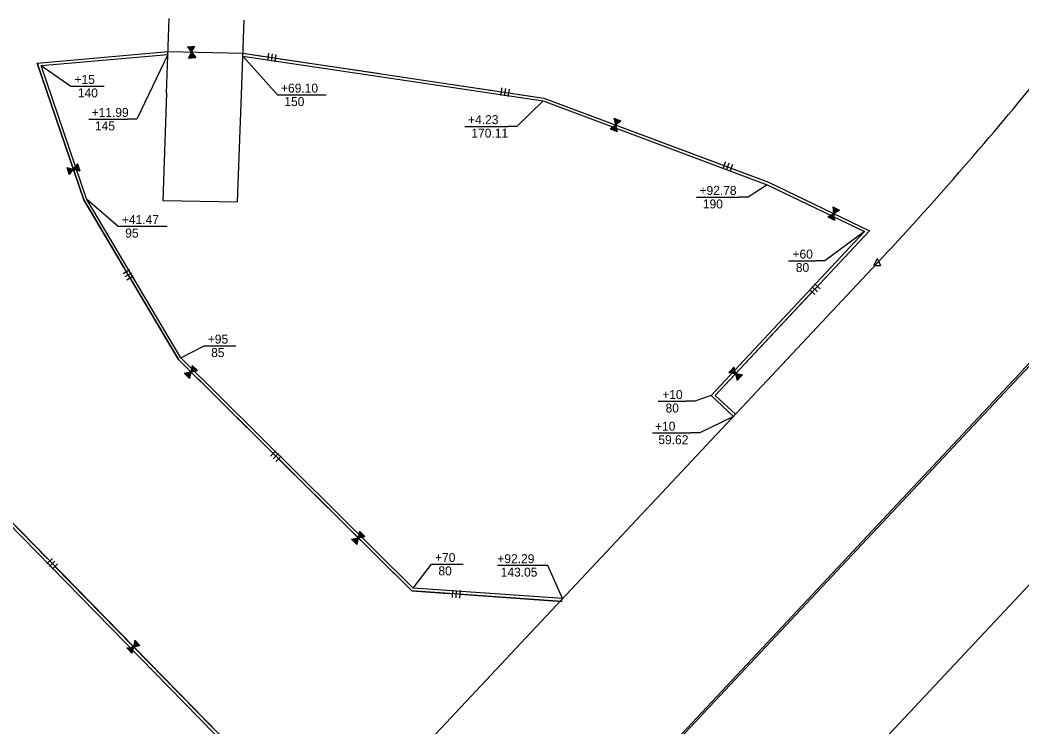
# Model space of a CAD drawing. Extents: x 979729 to 993523, y 1834148 to 1845433.
# Drawn here: x 991545 to 992215, y 1839035 to 1839507 of the extents above; entities that cross this region are included whole.
import ezdxf

# ---------------------------------------------------------------- set-up
doc = ezdxf.new("R2010")
doc.units = 0
for name, color, linetype in [('42', 7, 'Continuous'), ('51', 7, 'Continuous'), ('R_Draft', 7, 'Continuous'), ('S_EXIST_ROW', 7, 'Continuous')]:
    doc.layers.add(name, color=color, linetype=linetype)

msp = doc.modelspace()

# ---------------------------------------------------------------- linework, layer by layer
at = {"layer": '42'}
for p, q in [((991644.19, 1839486.32), (991694.18, 1839485.24)), ((991657.1, 1839489.43), (991659.92, 1839485.91)), ((991657.17, 1839489.38), (991657.2, 1839489.44)), ((991657.34, 1839489.19), (991657.5, 1839489.46)), ((991657.5, 1839488.96), (991657.8, 1839489.49)), ((991657.68, 1839488.77), (991658.1, 1839489.52)), ((991657.76, 1839481.96), (991659.92, 1839485.91)), ((991657.84, 1839488.54), (991658.39, 1839489.54)), ((991658, 1839488.31), (991658.69, 1839489.57)), ((991658.18, 1839488.11), (991658.99, 1839489.59)), ((991658.39, 1839487.98), (991659.21, 1839489.48)), ((991658.53, 1839487.71), (991659.59, 1839489.65)), ((991658.71, 1839487.52), (991659.89, 1839489.67)), ((991658.86, 1839487.27), (991660.19, 1839489.7)), ((991659.05, 1839487.1), (991660.49, 1839489.73)), ((991659.2, 1839486.85), (991660.79, 1839489.75)), ((991659.38, 1839486.65), (991661.09, 1839489.78)), ((991659.54, 1839486.42), (991661.39, 1839489.8)), ((991659.63, 1839485.34), (991662.04, 1839482.33)), ((991659.73, 1839486.25), (991661.69, 1839489.83)), ((991659.79, 1839485.54), (991662.34, 1839482.36)), ((991659.87, 1839486), (991661.99, 1839489.86)), ((991659.89, 1839485.82), (991662.64, 1839482.38)), ((991659.92, 1839485.91), (991662.09, 1839489.86)), ((991659.92, 1839485.91), (991662.74, 1839482.39)), ((991711.36, 1839485.21), (991710.63, 1839480.26)), ((991657.81, 1839482.02), (991657.85, 1839481.97)), ((991657.95, 1839482.24), (991658.15, 1839481.99)), ((991658.07, 1839482.49), (991658.45, 1839482.02)), ((991658.21, 1839482.71), (991658.75, 1839482.04)), ((991658.33, 1839482.97), (991659.05, 1839482.07)), ((991658.45, 1839483.22), (991659.35, 1839482.1)), ((991658.59, 1839483.44), (991659.64, 1839482.12)), ((991658.77, 1839483.61), (991659.84, 1839482.28)), ((991658.87, 1839483.9), (991660.24, 1839482.18)), ((991659.01, 1839484.12), (991660.54, 1839482.2)), ((991659.11, 1839484.39), (991660.84, 1839482.23)), ((991659.27, 1839484.59), (991661.14, 1839482.25)), ((991659.37, 1839484.87), (991661.44, 1839482.28)), ((991659.51, 1839485.09), (991661.74, 1839482.31)), ((991713.84, 1839484.84), (991713.1, 1839479.89)), ((991716.31, 1839484.47), (991715.57, 1839479.52)), ((991867.15, 1839462.02), (991866.41, 1839457.07)), ((991869.62, 1839461.65), (991868.88, 1839456.71)), ((991872.09, 1839461.28), (991871.36, 1839456.34)), ((991942.19, 1839441.76), (991943.22, 1839437.38)), ((991942.23, 1839441.69), (991942.28, 1839441.73)), ((991942.31, 1839441.44), (991942.56, 1839441.63)), ((991942.35, 1839441.17), (991942.84, 1839441.52)), ((991942.43, 1839440.91), (991943.13, 1839441.41)), ((991942.48, 1839440.64), (991943.41, 1839441.31)), ((991942.52, 1839440.36), (991943.69, 1839441.2)), ((991942.6, 1839440.11), (991943.97, 1839441.1)), ((991942.73, 1839439.9), (991944.12, 1839440.9)), ((991942.75, 1839439.6), (991944.53, 1839440.89)), ((991942.82, 1839439.35), (991944.81, 1839440.78)), ((991942.85, 1839439.06), (991945.1, 1839440.68)), ((991942.95, 1839438.82), (991945.38, 1839440.57)), ((991942.97, 1839438.53), (991945.66, 1839440.47)), ((991943.05, 1839438.28), (991945.94, 1839440.36)), ((991943.09, 1839438), (991946.22, 1839440.26)), ((991943.19, 1839437.77), (991946.5, 1839440.15)), ((991943.22, 1839437.48), (991946.78, 1839440.05)), ((991943.22, 1839437.38), (991946.88, 1839440.01)), ((991939.57, 1839434.74), (991943.22, 1839437.38)), ((991939.64, 1839434.77), (991939.65, 1839434.71)), ((991939.86, 1839434.91), (991939.93, 1839434.6)), ((991940.08, 1839435.09), (991940.21, 1839434.5)), ((991940.3, 1839435.22), (991940.5, 1839434.39)), ((991940.52, 1839435.4), (991940.78, 1839434.29)), ((991940.73, 1839435.58), (991941.06, 1839434.18)), ((991940.96, 1839435.72), (991941.34, 1839434.07)), ((991941.19, 1839435.8), (991941.58, 1839434.13)), ((991941.4, 1839436.01), (991941.9, 1839433.86)), ((991941.63, 1839436.15), (991942.19, 1839433.76)), ((991941.83, 1839436.35), (991942.47, 1839433.65)), ((991942.07, 1839436.46), (991942.75, 1839433.55)), ((991942.27, 1839436.67), (991943.03, 1839433.44)), ((991942.5, 1839436.81), (991943.31, 1839433.34)), ((991942.71, 1839436.99), (991943.59, 1839433.23)), ((991942.94, 1839437.1), (991943.87, 1839433.13)), ((991943.15, 1839437.3), (991944.15, 1839433.02)), ((991943.22, 1839437.38), (991944.25, 1839432.99)), ((992016.68, 1839412.55), (992014.93, 1839407.87)), ((992019.02, 1839411.68), (992017.27, 1839406.99)), ((992021.36, 1839410.8), (992019.61, 1839406.12)), ((992085.11, 1839375.82), (992088.99, 1839378.11)), ((992088.37, 1839382.57), (992088.99, 1839378.11)), ((992088.4, 1839382.5), (992088.46, 1839382.53)), ((992088.46, 1839382.24), (992088.73, 1839382.4)), ((992088.47, 1839381.96), (992089, 1839382.27)), ((992088.53, 1839381.71), (992089.27, 1839382.14)), ((992088.55, 1839381.43), (992089.54, 1839382.01)), ((992088.57, 1839381.15), (992089.81, 1839381.88)), ((992088.62, 1839380.89), (992090.08, 1839381.75)), ((992088.72, 1839380.37), (992090.62, 1839381.49)), ((992088.74, 1839380.67), (992090.21, 1839381.53)), ((992088.77, 1839379.82), (992091.16, 1839381.23)), ((992088.78, 1839380.11), (992090.89, 1839381.36)), ((992088.85, 1839379.57), (992091.43, 1839381.1)), ((992088.85, 1839379.28), (992091.7, 1839380.97)), ((992088.9, 1839379.03), (992091.97, 1839380.84)), ((992088.92, 1839378.75), (992092.24, 1839380.71)), ((992088.99, 1839378.11), (992092.88, 1839380.4)), ((992088.99, 1839378.11), (992089.62, 1839373.65)), ((992089, 1839378.5), (992092.51, 1839380.57)), ((992089, 1839378.21), (992092.78, 1839380.44)), ((992085.19, 1839375.84), (992085.2, 1839375.78)), ((992085.42, 1839375.96), (992085.47, 1839375.65)), ((992085.65, 1839376.12), (992085.74, 1839375.52)), ((992085.89, 1839376.23), (992086.01, 1839375.39)), ((992086.12, 1839376.39), (992086.28, 1839375.26)), ((992086.35, 1839376.55), (992086.55, 1839375.12)), ((992086.59, 1839376.67), (992086.82, 1839374.99)), ((992086.83, 1839376.72), (992087.07, 1839375.03)), ((992087.06, 1839376.92), (992087.36, 1839374.73)), ((992087.29, 1839377.03), (992087.63, 1839374.6)), ((992087.52, 1839377.22), (992087.9, 1839374.47)), ((992087.76, 1839377.31), (992088.17, 1839374.34)), ((992087.99, 1839377.49), (992088.44, 1839374.21)), ((992088.22, 1839377.61), (992088.71, 1839374.08)), ((992088.45, 1839377.77), (992088.99, 1839373.95)), ((992088.69, 1839377.86), (992089.26, 1839373.82)), ((992088.92, 1839378.04), (992089.53, 1839373.69)), ((992076.46, 1839324), (992072.81, 1839327.41)), ((992078.17, 1839325.82), (992074.51, 1839329.24)), ((992079.87, 1839327.65), (992076.22, 1839331.06)), ((992023.4, 1839270.93), (992018.95, 1839271.67)), ((992023.36, 1839271.02), (992019.02, 1839271.74)), ((992023.25, 1839271.3), (992019.22, 1839271.96)), ((992023.23, 1839271.55), (992019.43, 1839272.18)), ((992023.15, 1839271.82), (992019.63, 1839272.4)), ((992023.11, 1839272.08), (992019.84, 1839272.62)), ((992023, 1839272.35), (992020.04, 1839272.84)), ((992022.99, 1839272.61), (992020.25, 1839273.06)), ((992022.87, 1839272.88), (992020.45, 1839273.28)), ((992022.83, 1839273.14), (992020.66, 1839273.5)), ((992022.72, 1839273.41), (992021.03, 1839273.69)), ((992022.74, 1839273.66), (992021.07, 1839273.94)), ((992022.69, 1839273.92), (992021.28, 1839274.16)), ((992022.61, 1839274.19), (992021.48, 1839274.37)), ((992022.53, 1839274.45), (992021.69, 1839274.59)), ((992022.49, 1839274.71), (992021.89, 1839274.81)), ((992022.41, 1839274.98), (992022.1, 1839275.03)), ((992022.37, 1839275.24), (992022.3, 1839275.25)), ((992022.37, 1839275.32), (992023.4, 1839270.93)), ((992023.4, 1839270.93), (992024.43, 1839266.55)), ((992027.84, 1839270.2), (992023.4, 1839270.93)), ((992023.49, 1839270.9), (992024.5, 1839266.62)), ((992023.77, 1839270.81), (992024.7, 1839266.84)), ((992024.02, 1839270.81), (992024.91, 1839267.06)), ((992024.3, 1839270.75), (992025.11, 1839267.28)), ((992024.56, 1839270.72), (992025.32, 1839267.5)), ((992024.84, 1839270.63), (992025.52, 1839267.71)), ((992025.09, 1839270.63), (992025.73, 1839267.93)), ((992025.37, 1839270.54), (992025.93, 1839268.15)), ((992025.63, 1839270.52), (992026.14, 1839268.37)), ((992025.91, 1839270.42), (992026.31, 1839268.75)), ((992026.16, 1839270.46), (992026.55, 1839268.81)), ((992026.42, 1839270.43), (992026.75, 1839269.03)), ((992026.7, 1839270.37), (992026.96, 1839269.25)), ((992026.97, 1839270.3), (992027.16, 1839269.47)), ((992027.23, 1839270.28), (992027.37, 1839269.69)), ((992027.5, 1839270.22), (992027.57, 1839269.91)), ((992027.76, 1839270.19), (992027.78, 1839270.13))]:
    msp.add_line(p, q, dxfattribs=at)
for points in [[(991556.68, 1839478.69), (991644.19, 1839486.32)], [(991556.68, 1839478.69), (991644.19, 1839486.32), (991694.18, 1839485.24), (991708.52, 1839483.1)], [(991657.1, 1839489.43), (991662.09, 1839489.86)], [(991694.18, 1839485.24), (991895.33, 1839455.3), (992045.44, 1839399.12), (992112.88, 1839366.59)], [(991907.63, 1839118.73), (991807.07, 1839125.82), (991651.09, 1839280.5), (991587.82, 1839387.14), (991556.68, 1839478.69)], [(991657.76, 1839481.96), (991662.74, 1839482.39)], [(991715.94, 1839482), (991785.64, 1839471.62)], [(991828.17, 1839465.29), (991864.31, 1839459.92)], [(991871.72, 1839458.81), (991895.33, 1839455.3), (992013.46, 1839411.09)], [(991942.19, 1839441.76), (991946.88, 1839440.01)], [(991939.57, 1839434.74), (991944.25, 1839432.99)], [(992020.49, 1839408.46), (992045.44, 1839399.12), (992112.88, 1839366.59), (992079.76, 1839331.18)], [(991382.17, 1839394.42), (991468.64, 1839244.34), (991726.6, 1838980.6), (991714.1, 1838911.75)], [(992088.37, 1839382.57), (992092.88, 1839380.4)], [(992085.11, 1839375.82), (992089.62, 1839373.65)], [(992112.88, 1839366.59), (992009.91, 1839256.52), (992023.34, 1839243.96)], [(992074.63, 1839325.7), (992009.91, 1839256.52), (992023.34, 1839243.96)], [(992022.37, 1839275.32), (992018.95, 1839271.67)], [(992027.84, 1839270.2), (992024.43, 1839266.55)]]:
    msp.add_lwpolyline(points, dxfattribs=at)
at = {"layer": '51'}
for p, q in [((991576.48, 1839408.84), (991580.83, 1839407.69)), ((991576.55, 1839408.81), (991576.51, 1839408.76)), ((991576.8, 1839408.72), (991576.6, 1839408.47)), ((991577.07, 1839408.67), (991576.7, 1839408.19)), ((991577.32, 1839408.58), (991576.8, 1839407.9)), ((991577.59, 1839408.53), (991576.89, 1839407.62)), ((991577.86, 1839408.47), (991576.99, 1839407.33)), ((991578.12, 1839408.39), (991577.09, 1839407.05)), ((991578.32, 1839408.25), (991577.28, 1839406.9)), ((991578.62, 1839408.23), (991577.28, 1839406.48)), ((991578.87, 1839408.14), (991577.38, 1839406.2)), ((991579.16, 1839408.11), (991577.47, 1839405.91)), ((991579.39, 1839408), (991577.57, 1839405.63)), ((991579.69, 1839407.97), (991577.67, 1839405.34)), ((991579.93, 1839407.88), (991577.76, 1839405.06)), ((991580.21, 1839407.83), (991577.86, 1839404.77)), ((991580.44, 1839407.72), (991577.96, 1839404.49)), ((991580.73, 1839407.69), (991578.05, 1839404.21)), ((991580.83, 1839407.69), (991578.09, 1839404.11)), ((991583.58, 1839411.26), (991580.83, 1839407.69)), ((991580.83, 1839407.69), (991585.19, 1839406.53)), ((991580.91, 1839407.75), (991585.15, 1839406.62)), ((991581.12, 1839407.95), (991585.06, 1839406.9)), ((991581.24, 1839408.18), (991584.96, 1839407.19)), ((991581.42, 1839408.39), (991584.86, 1839407.47)), ((991581.57, 1839408.61), (991584.77, 1839407.76)), ((991581.78, 1839408.81), (991584.67, 1839408.04)), ((991581.9, 1839409.04), (991584.57, 1839408.33)), ((991582.11, 1839409.24), (991584.48, 1839408.61)), ((991582.25, 1839409.46), (991584.38, 1839408.9)), ((991582.47, 1839409.66), (991584.12, 1839409.22)), ((991582.55, 1839409.9), (991584.19, 1839409.46)), ((991582.7, 1839410.12), (991584.09, 1839409.75)), ((991582.88, 1839410.33), (991583.99, 1839410.03)), ((991583.07, 1839410.54), (991583.9, 1839410.32)), ((991583.21, 1839410.76), (991583.8, 1839410.6)), ((991583.4, 1839410.97), (991583.7, 1839410.89)), ((991583.54, 1839411.19), (991583.61, 1839411.17)), ((991618.44, 1839340.43), (991614.14, 1839337.88)), ((991619.72, 1839338.28), (991615.42, 1839335.73)), ((991620.99, 1839336.13), (991616.69, 1839333.58)), ((991655.05, 1839271.29), (991659.47, 1839272.19)), ((991655.13, 1839271.29), (991655.12, 1839271.22)), ((991655.39, 1839271.32), (991655.33, 1839271.01)), ((991655.66, 1839271.39), (991655.55, 1839270.8)), ((991655.92, 1839271.43), (991655.76, 1839270.59)), ((991656.19, 1839271.5), (991655.97, 1839270.37)), ((991656.46, 1839271.57), (991656.19, 1839270.16)), ((991656.72, 1839271.61), (991656.4, 1839269.95)), ((991656.97, 1839271.58), (991656.64, 1839269.9)), ((991657.25, 1839271.69), (991656.83, 1839269.53)), ((991657.51, 1839271.72), (991657.04, 1839269.32)), ((991657.78, 1839271.83), (991657.25, 1839269.11)), ((991658.04, 1839271.83), (991657.47, 1839268.89)), ((991658.32, 1839271.93), (991657.68, 1839268.68)), ((991658.58, 1839271.97), (991657.89, 1839268.47)), ((991658.85, 1839272.04), (991658.11, 1839268.26)), ((991659.1, 1839272.05), (991658.32, 1839268.05)), ((991659.38, 1839272.15), (991658.53, 1839267.84)), ((991659.47, 1839272.19), (991658.6, 1839267.77)), ((991660.33, 1839276.61), (991659.47, 1839272.19)), ((991659.47, 1839272.19), (991663.88, 1839273.09)), ((991659.51, 1839272.28), (991663.81, 1839273.16)), ((991659.61, 1839272.81), (991663.39, 1839273.58)), ((991659.61, 1839272.56), (991663.6, 1839273.37)), ((991659.68, 1839273.08), (991663.17, 1839273.8)), ((991659.71, 1839273.34), (991662.96, 1839274.01)), ((991659.81, 1839273.62), (991662.75, 1839274.22)), ((991659.82, 1839273.88), (991662.53, 1839274.43)), ((991659.92, 1839274.15), (991662.32, 1839274.64)), ((991659.95, 1839274.41), (991662.11, 1839274.85)), ((991660.03, 1839274.94), (991661.68, 1839275.28)), ((991660.06, 1839275.2), (991661.47, 1839275.49)), ((991660.06, 1839274.69), (991661.73, 1839275.03)), ((991660.13, 1839275.47), (991661.25, 1839275.7)), ((991660.2, 1839275.74), (991661.04, 1839275.91)), ((991660.23, 1839276), (991660.83, 1839276.12)), ((991660.3, 1839276.27), (991660.61, 1839276.33)), ((991660.34, 1839276.53), (991660.4, 1839276.55)), ((991716.26, 1839219.39), (991712.74, 1839215.84)), ((991718.03, 1839217.63), (991714.51, 1839214.08)), ((991719.81, 1839215.87), (991716.29, 1839212.32)), ((991772.17, 1839165.71), (991771.3, 1839161.29)), ((991771.78, 1839163.51), (991773.94, 1839163.95)), ((991771.86, 1839164.04), (991773.51, 1839164.38)), ((991771.89, 1839164.3), (991773.3, 1839164.59)), ((991771.89, 1839163.79), (991773.57, 1839164.13)), ((991771.96, 1839164.57), (991773.09, 1839164.8)), ((991772.04, 1839164.84), (991772.87, 1839165.01)), ((991772.07, 1839165.1), (991772.66, 1839165.22)), ((991772.14, 1839165.37), (991772.45, 1839165.43)), ((991772.17, 1839165.63), (991772.23, 1839165.64)), ((991766.89, 1839160.38), (991771.3, 1839161.29)), ((991766.97, 1839160.38), (991766.95, 1839160.32)), ((991767.23, 1839160.42), (991767.17, 1839160.11)), ((991767.5, 1839160.49), (991767.38, 1839159.9)), ((991767.76, 1839160.52), (991767.59, 1839159.68)), ((991768.03, 1839160.6), (991767.81, 1839159.47)), ((991768.3, 1839160.67), (991768.02, 1839159.26)), ((991768.56, 1839160.71), (991768.23, 1839159.05)), ((991768.81, 1839160.68), (991768.48, 1839159)), ((991769.08, 1839160.79), (991768.66, 1839158.63)), ((991769.34, 1839160.82), (991768.87, 1839158.41)), ((991769.62, 1839160.92), (991769.09, 1839158.2)), ((991769.88, 1839160.93), (991769.3, 1839157.99)), ((991770.15, 1839161.03), (991769.51, 1839157.78)), ((991770.41, 1839161.07), (991769.73, 1839157.57)), ((991770.68, 1839161.14), (991769.94, 1839157.36)), ((991770.94, 1839161.15), (991770.15, 1839157.15)), ((991771.21, 1839161.25), (991770.37, 1839156.93)), ((991771.3, 1839161.29), (991770.44, 1839156.86)), ((991771.3, 1839161.29), (991775.72, 1839162.19)), ((991771.34, 1839161.38), (991775.65, 1839162.26)), ((991771.44, 1839161.91), (991775.22, 1839162.68)), ((991771.44, 1839161.66), (991775.43, 1839162.47)), ((991771.52, 1839162.18), (991775.01, 1839162.89)), ((991771.55, 1839162.44), (991774.79, 1839163.11)), ((991771.65, 1839162.97), (991774.37, 1839163.53)), ((991771.65, 1839162.72), (991774.58, 1839163.32)), ((991771.75, 1839163.25), (991774.16, 1839163.74)), ((991566.87, 1839147.49), (991563.29, 1839143.99)), ((991568.61, 1839145.7), (991565.04, 1839142.21)), ((991570.36, 1839143.91), (991566.79, 1839140.42)), ((991834.31, 1839126.4), (991833.96, 1839121.42)), ((991836.8, 1839126.23), (991836.45, 1839121.24)), ((991839.3, 1839126.05), (991838.94, 1839121.07)), ((991621.95, 1839092.96), (991621.02, 1839088.55)), ((991621.28, 1839089.7), (991624.54, 1839090.31)), ((991621.38, 1839089.97), (991624.33, 1839090.53)), ((991621.39, 1839090.23), (991624.12, 1839090.74)), ((991621.5, 1839090.5), (991623.91, 1839090.96)), ((991621.53, 1839090.76), (991623.7, 1839091.17)), ((991621.62, 1839091.29), (991623.28, 1839091.6)), ((991621.64, 1839091.04), (991623.32, 1839091.36)), ((991621.65, 1839091.55), (991623.07, 1839091.82)), ((991621.73, 1839091.82), (991622.86, 1839092.03)), ((991621.8, 1839092.09), (991622.65, 1839092.25)), ((991621.84, 1839092.35), (991622.43, 1839092.46)), ((991621.92, 1839092.62), (991622.23, 1839092.68)), ((991621.95, 1839092.88), (991622.01, 1839092.89)), ((991616.59, 1839087.71), (991621.02, 1839088.55)), ((991616.67, 1839087.71), (991616.65, 1839087.65)), ((991616.93, 1839087.74), (991616.86, 1839087.43)), ((991617.2, 1839087.81), (991617.07, 1839087.22)), ((991617.46, 1839087.84), (991617.28, 1839087)), ((991617.73, 1839087.91), (991617.49, 1839086.79)), ((991618, 1839087.98), (991617.7, 1839086.57)), ((991618.26, 1839088.01), (991617.91, 1839086.36)), ((991618.51, 1839087.98), (991618.16, 1839086.31)), ((991618.79, 1839088.08), (991618.33, 1839085.93)), ((991619.05, 1839088.11), (991618.54, 1839085.71)), ((991619.33, 1839088.21), (991618.75, 1839085.5)), ((991619.58, 1839088.21), (991618.96, 1839085.28)), ((991619.86, 1839088.31), (991619.17, 1839085.07)), ((991620.12, 1839088.34), (991619.38, 1839084.85)), ((991620.39, 1839088.41), (991619.59, 1839084.64)), ((991620.65, 1839088.41), (991619.8, 1839084.42)), ((991620.92, 1839088.51), (991620.01, 1839084.21)), ((991621.02, 1839088.55), (991620.08, 1839084.14)), ((991621.02, 1839088.55), (991625.45, 1839089.38)), ((991621.06, 1839088.64), (991625.38, 1839089.45)), ((991621.16, 1839088.91), (991625.17, 1839089.67)), ((991621.17, 1839089.17), (991624.96, 1839089.88)), ((991621.24, 1839089.44), (991624.75, 1839090.1))]:
    msp.add_line(p, q, dxfattribs=at)
for points in [[(991556.68, 1839478.69), (991587.82, 1839387.14), (991615.01, 1839341.3)], [(991907.77, 1839120.72), (991807.95, 1839127.76), (991652.68, 1839281.74), (991589.65, 1839387.98), (991559.39, 1839476.92), (991644.12, 1839484.31)], [(991694.11, 1839483.22), (991894.83, 1839453.35), (992044.65, 1839397.28), (992109.56, 1839365.97)], [(991576.48, 1839408.84), (991578.09, 1839404.11)], [(991583.58, 1839411.26), (991585.19, 1839406.53)], [(991381, 1839392.44), (991467.04, 1839243.12), (991724.44, 1838979.94), (991712.13, 1838912.1)], [(992109.56, 1839365.97), (992007.09, 1839256.43), (992021.97, 1839242.5)], [(991618.84, 1839334.85), (991651.09, 1839280.5), (991712.72, 1839219.38)], [(991655.05, 1839271.29), (991658.6, 1839267.77)], [(991660.33, 1839276.61), (991663.88, 1839273.09)], [(991461.36, 1839256.97), (991468.64, 1839244.34), (991563.33, 1839147.53)], [(991718.05, 1839214.1), (991807.07, 1839125.82), (991831.64, 1839124.09)], [(991772.17, 1839165.71), (991775.72, 1839162.19)], [(991766.89, 1839160.38), (991770.44, 1839156.86)], [(991568.58, 1839142.17), (991673.46, 1839034.93)], [(991839.12, 1839123.56), (991907.63, 1839118.73)], [(991621.95, 1839092.96), (991625.45, 1839089.38)], [(991616.59, 1839087.71), (991620.08, 1839084.14)]]:
    msp.add_lwpolyline(points, dxfattribs=at)
at = {"layer": 'R_Draft'}
for p, q in [((991585.31, 1839463.21), (991601.46, 1839463.21)), ((991723.31, 1839457.4), (991749.89, 1839457.4)), ((991591.35, 1839441.16), (991617.39, 1839441.16)), ((991842.59, 1839436.32), (991871.21, 1839436.32)), ((991997.26, 1839389.01), (992025.88, 1839389.01)), ((991616.97, 1839369.53), (991643.55, 1839369.53)), ((992058.77, 1839346.48), (992077.2, 1839346.48)), ((991674.38, 1839289.64), (991689.49, 1839289.64)), ((991971.74, 1839252.59), (991990.17, 1839252.59)), ((991968.02, 1839231.42), (991993.56, 1839231.42)), ((991826.27, 1839143.74), (991841.38, 1839143.74)), ((991891.9, 1839142.89), (991864.26, 1839142.89))]:
    msp.add_line(p, q, dxfattribs=at)
for points in [[(991644.12, 1839484.31), (991623.39, 1839441.16), (991617.39, 1839441.16)], [(991694.11, 1839483.22), (991717.31, 1839457.4), (991723.31, 1839457.4)], [(991559.39, 1839476.92), (991579.31, 1839463.21), (991585.31, 1839463.21)], [(991894.83, 1839453.35), (991877.21, 1839436.32), (991871.21, 1839436.32)], [(992044.65, 1839397.28), (992031.88, 1839389.01), (992025.88, 1839389.01)], [(991589.65, 1839387.98), (991610.97, 1839369.53), (991616.97, 1839369.53)], [(992109.56, 1839365.97), (992083.2, 1839346.48), (992077.2, 1839346.48)], [(991652.68, 1839281.74), (991668.38, 1839289.64), (991674.38, 1839289.64)], [(992007.09, 1839256.43), (991996.17, 1839252.59), (991990.17, 1839252.59)], [(992021.97, 1839242.5), (991999.56, 1839231.42), (991993.56, 1839231.42)], [(991807.95, 1839127.76), (991820.27, 1839143.74), (991826.27, 1839143.74)], [(991907.77, 1839120.72), (991897.9, 1839142.89), (991891.9, 1839142.89)]]:
    msp.add_lwpolyline(points, dxfattribs=at)
at = {"layer": 'S_EXIST_ROW'}
for p, q in [((990293.19, 1837222.17), (993190.16, 1840310.88)), ((990366.13, 1837153.76), (993263.1, 1840242.47)), ((991643.19, 1839458.63), (991644.99, 1839508.44)), ((991693.19, 1839457.58), (991694.98, 1839507.41)), ((991690.61, 1839385.82), (991693.19, 1839457.58)), ((987322.66, 1834231.42), (992118.05, 1839344.95)), ((992118.06, 1839347.98), (992115.8, 1839343.44)), ((992118.05, 1839344.95), (992118.05, 1839344.95)), ((992118.06, 1839347.98), (992120.29, 1839343.44)), ((992115.8, 1839343.44), (992120.29, 1839343.44)), ((987410.19, 1834149.33), (992205.58, 1839262.87))]:
    msp.add_line(p, q, dxfattribs=at)
msp.add_lwpolyline([(991643.19, 1839458.63), (991640.61, 1839386.89), (991690.61, 1839385.82)], dxfattribs=at)
for radius in [0.0768, 0.0384]:
    msp.add_circle((992118.05, 1839344.95), radius, dxfattribs=at)
for radius in [2266.7, 2386.7]:
    msp.add_arc((990464.64, 1840895.49), radius, 316.83896, 320.96135, dxfattribs=at)

# ---------------------------------------------------------------- texts
at = {"layer": 'R_Draft'}
for s, p in [('+15', (991581.68, 1839464.71)), (' 140', (991581.68, 1839455.71)), ('+69.10', (991719.69, 1839458.9)), (' 150', (991719.69, 1839449.9)), ('+11.99', (991593.12, 1839442.66)), (' 145', (991593.12, 1839433.66)), ('+4.23', (991844.68, 1839437.82)), (' 170.11', (991844.68, 1839428.82)), ('+92.78', (991999.35, 1839390.51)), (' 190', (991999.35, 1839381.51)), ('+41.47', (991613.35, 1839371.03)), (' 95', (991613.35, 1839362.03)), ('+60', (992061.48, 1839347.98)), (' 80', (992061.48, 1839338.98)), ('+95', (991670.76, 1839291.14)), (' 85', (991670.76, 1839282.14)), ('+10', (991974.45, 1839254.09)), (' 80', (991974.45, 1839245.09)), ('+10', (991969.62, 1839232.92)), (' 59.62', (991969.62, 1839223.92)), ('+70', (991822.64, 1839145.24)), ('+92.29', (991864.26, 1839144.39)), (' 80', (991822.64, 1839136.24)), (' 143.05', (991864.26, 1839135.39))]:
    msp.add_text(s, height=6, rotation=360, dxfattribs=at).set_placement(p)

doc.saveas('drawing.dxf')
